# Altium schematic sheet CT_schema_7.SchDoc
size 373 x 245 mm
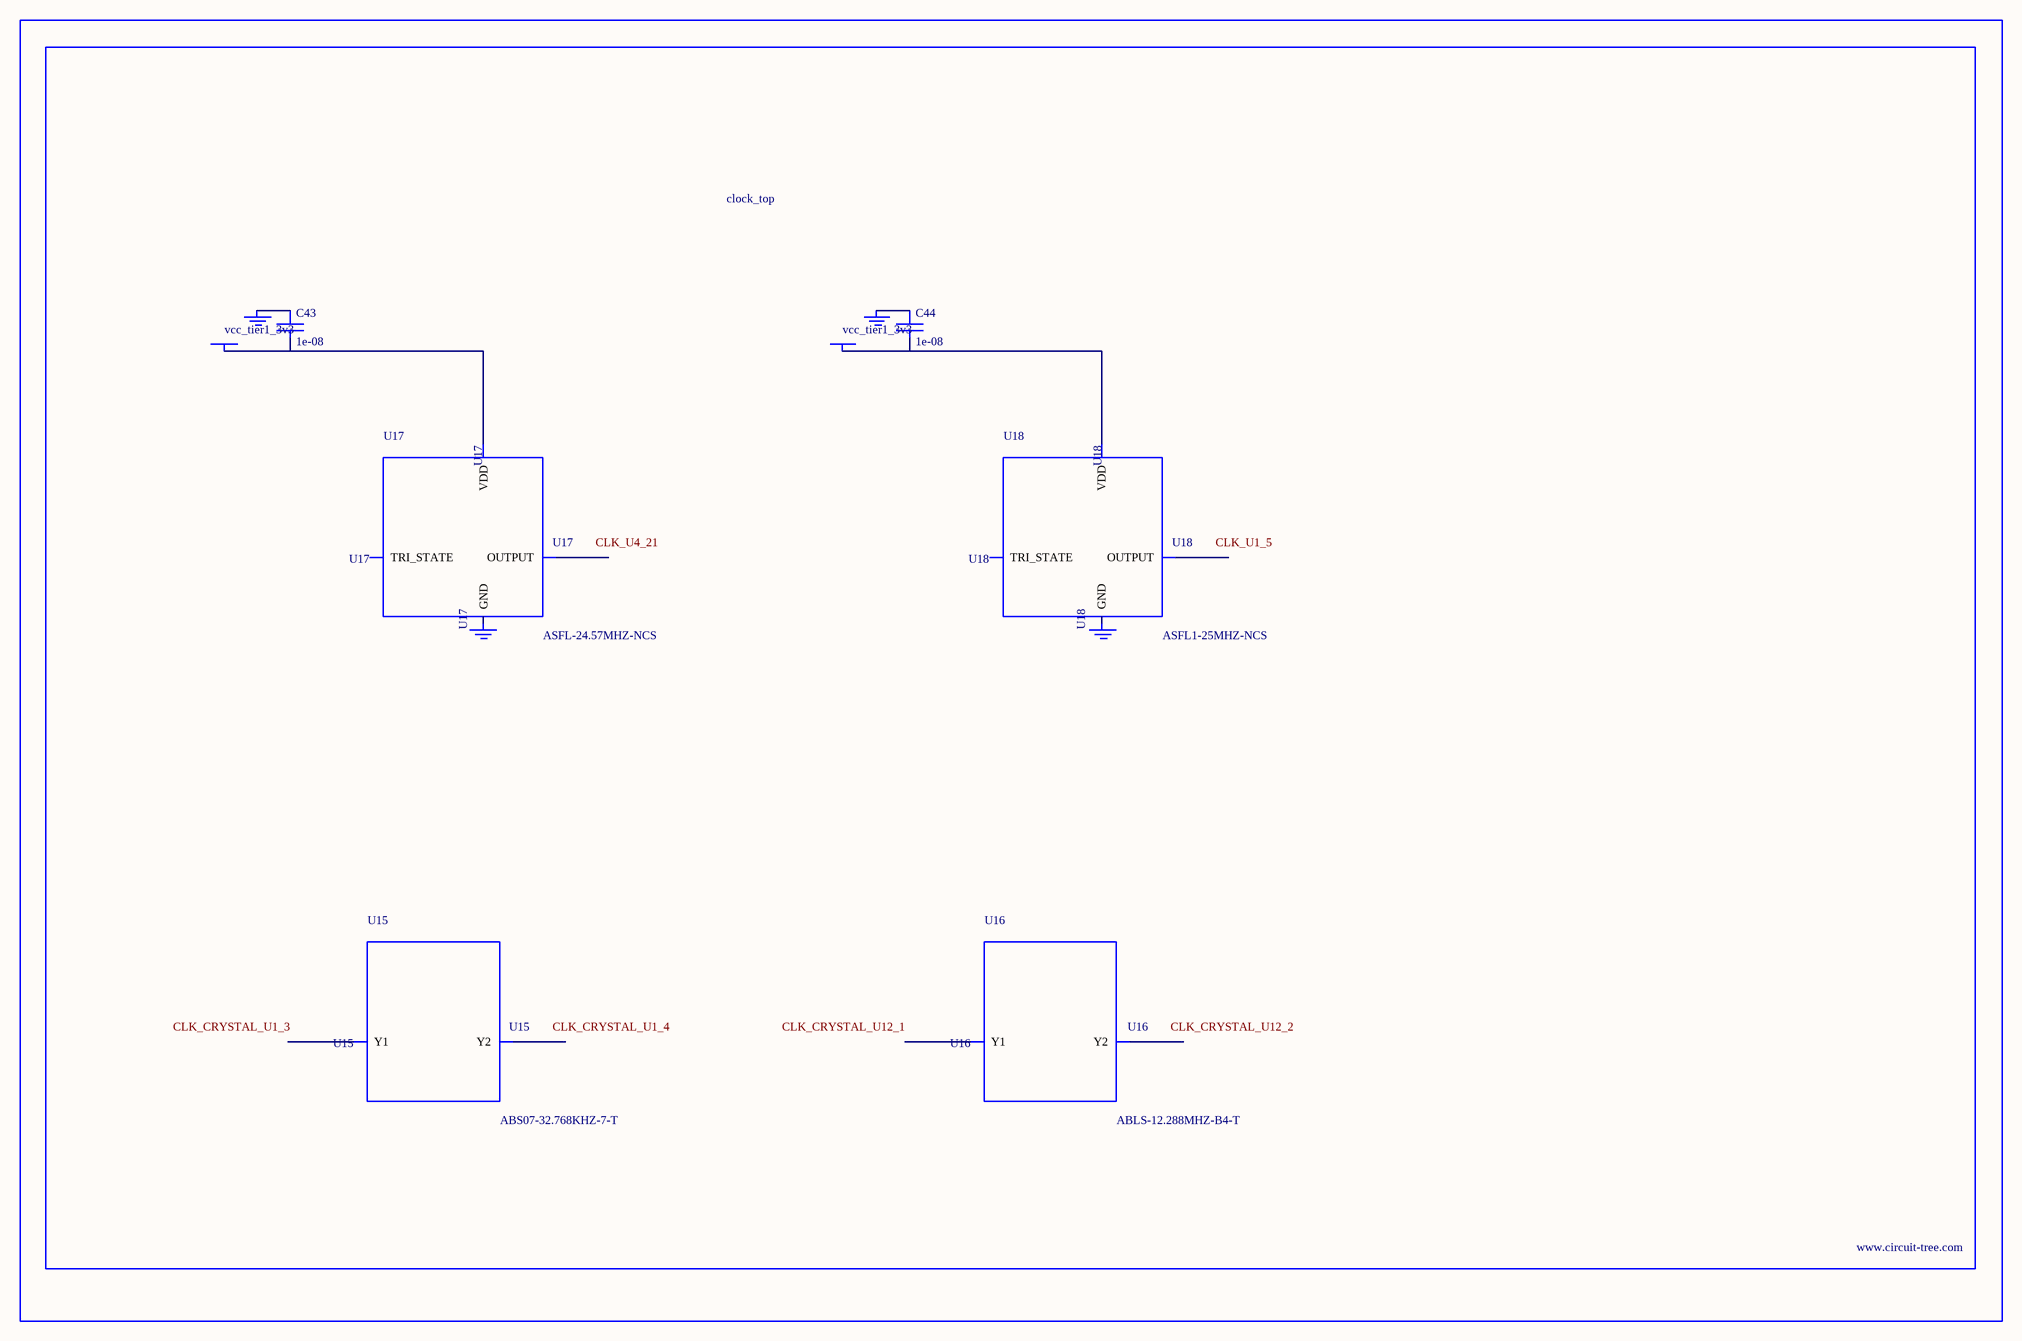
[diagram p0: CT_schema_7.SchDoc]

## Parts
BORDER6  (no value)
C43  1e-08  [C0402]
C44  1e-08  [C0402]
GND_INSTANCE_6_0  (no value)
GND_INSTANCE_6_1  (no value)
GND_INSTANCE_6_2  (no value)
GND_INSTANCE_6_3  (no value)
POWER_INSTANCE_6_0  vcc_tier1_3v3
POWER_INSTANCE_6_1  vcc_tier1_3v3
U15  ABS07-32.768KHZ-7-T  [ABS07-32.768KHZ-7-T]
U16  ABLS-12.288MHZ-B4-T  [ABLS-12.288MHZ-B4-T]
U17  ASFL-24.57MHZ-NCS  [ASFL1]
U18  ASFL1-25MHZ-NCS  [ASFL1]

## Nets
NetC43_1: C43.1 GND_INSTANCE_6_0.0(GND)
NetC43_2: C43.2 POWER_INSTANCE_6_0.0(PWR) U17.4(VDD)
NetC44_1: C44.1 GND_INSTANCE_6_2.0(GND)
NetC44_2: C44.2 POWER_INSTANCE_6_1.0(PWR) U18.4(VDD)

Not connected (* = marked no-connect by the designer): GND_INSTANCE_6_1 0(GND); GND_INSTANCE_6_3 0(GND); U15 1(Y1) 2(Y2); U16 1(Y1) 2(Y2); U17 1(TRI_STATE) 2(GND) 3(OUTPUT); U18 1(TRI_STATE) 2(GND) 3(OUTPUT)

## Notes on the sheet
- Labels drawn without touching a wire or pin: CLK_CRYSTAL_U1_3, CLK_CRYSTAL_U1_4, CLK_CRYSTAL_U12_1, CLK_CRYSTAL_U12_2, CLK_U1_5, CLK_U4_21

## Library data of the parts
BORDER6 = BORDER_PAGE6
C43 C44 = C0402C103K3RAC
GND_INSTANCE_6_0-GND_INSTANCE_6_3 = GND
POWER_INSTANCE_6_0 POWER_INSTANCE_6_1 = PWR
